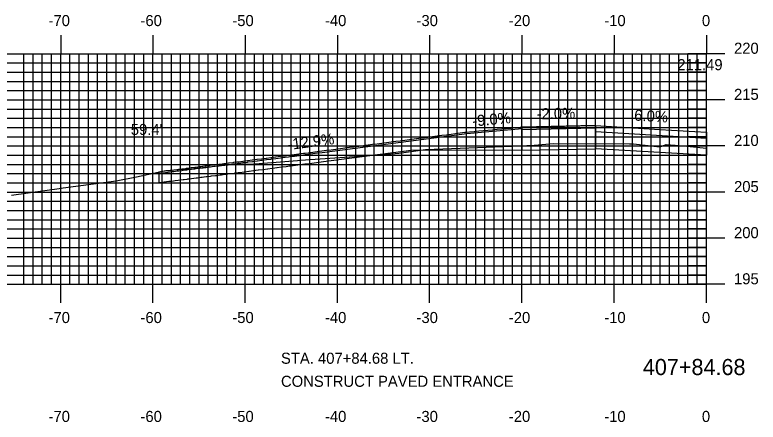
# Model space of a CAD drawing. Extents: x 852529 to 852872, y 364785 to 365005.
# Drawn here: x 852619.8 to 852700.3, y 364846.2 to 364890.4 of the extents above; entities that cross this region are included whole.
import ezdxf

# ---------------------------------------------------------------- set-up
doc = ezdxf.new("R2010")
doc.units = 0
for name, color, linetype in [('ANNOTATION', 7, 'Continuous'), ('D_Roadway_Centerline', 7, 'Continuous'), ('D_Roadway_Centerline_Text', 7, 'Continuous'), ('D_Roadway_Drive_Paved_LT', 7, 'Continuous'), ('D_Roadway_Drive_SubGrade', 7, 'Continuous'), ('D_Roadway_Edge_Shoulder', 7, 'Continuous'), ('D_Roadway_SlopeLines', 7, 'Continuous'), ('D_Text_Standard', 7, 'Continuous'), ('H_V ANNOTATION', 7, 'Continuous'), ('MAJOR', 7, 'Continuous'), ('MINOR', 7, 'Continuous'), ('S_Roadway_Centerline', 7, 'Continuous')]:
    doc.layers.add(name, color=color, linetype=linetype)

msp = doc.modelspace()

# ---------------------------------------------------------------- linework, layer by layer
at = {"layer": 'ANNOTATION'}
for p, q in [((852674.731, 364878.208), (852674.731, 364875.708)), ((852682.731, 364878.368), (852682.731, 364877.701)), ((852682.731, 364878.368), (852682.731, 364875.868)), ((852674.731, 364875.708), (852682.731, 364875.868))]:
    msp.add_line(p, q, dxfattribs=at)
for points in [[(852694.731, 364877.648), (852694.731, 364876.981), (852682.731, 364877.701)], [(852694.731, 364877.648), (852694.731, 364875.148), (852682.731, 364875.868)]]:
    msp.add_lwpolyline(points, dxfattribs=at)
at = {"layer": 'D_Roadway_Centerline'}
for points in [[(852635.377, 364873.373), (852635.536, 364873.392), (852635.757, 364873.42), (852636.076, 364873.46), (852636.283, 364873.485), (852636.316, 364873.489), (852636.37, 364873.496), (852636.533, 364873.515), (852636.807, 364873.55), (852636.992, 364873.572), (852637.33, 364873.615), (852637.503, 364873.635), (852637.851, 364873.68), (852637.983, 364873.696), (852638.274, 364873.733), (852638.303, 364873.736), (852638.371, 364873.745), (852638.522, 364873.763), (852638.889, 364873.81), (852639.271, 364873.858), (852639.406, 364873.875), (852639.797, 364873.925), (852639.922, 364873.94), (852640.105, 364873.963), (852640.16, 364873.97), (852640.375, 364873.997), (852640.437, 364874.005), (852640.845, 364874.057), (852640.95, 364874.07), (852641.366, 364874.123), (852641.463, 364874.135), (852641.886, 364874.189), (852641.974, 364874.2), (852642.021, 364874.206), (852642.03, 364874.207), (852642.414, 364874.256), (852642.485, 364874.265), (852642.922, 364874.321), (852642.994, 364874.33), (852643.438, 364874.387), (852643.503, 364874.395), (852643.843, 364874.439), (852643.887, 364874.444), (852643.997, 364874.458), (852644.01, 364874.46), (852644.467, 364874.519), (852644.517, 364874.525), (852644.979, 364874.584), (852645.023, 364874.59), (852645.49, 364874.65), (852645.528, 364874.655), (852645.718, 364874.679), (852645.733, 364874.681), (852646.014, 364874.717), (852646.033, 364874.72), (852646.509, 364874.781), (852646.537, 364874.785), (852647.017, 364874.847), (852647.041, 364874.85), (852647.524, 364874.912), (852647.544, 364874.915), (852647.569, 364874.918), (852647.57, 364874.918), (852648.031, 364874.978), (852648.046, 364874.98), (852648.535, 364875.043), (852648.548, 364875.045), (852649.04, 364875.109), (852649.05, 364875.11), (852649.395, 364875.155), (852649.401, 364875.155), (852649.549, 364875.174), (852649.551, 364875.175), (852650.046, 364875.239), (852650.052, 364875.24), (852650.549, 364875.304), (852650.552, 364875.305), (852651.051, 364875.369), (852651.053, 364875.37), (852651.227, 364875.392), (852651.227, 364875.392), (852651.552, 364875.435), (852651.553, 364875.435), (852652.053, 364875.5), (852652.053, 364875.5), (852652.288, 364875.53), (852652.553, 364875.565), (852652.553, 364875.565), (852653.051, 364875.629), (852653.053, 364875.63), (852653.053, 364875.63), (852653.053, 364875.63), (852653.553, 364875.695), (852653.553, 364875.695), (852654.053, 364875.76), (852654.053, 364875.76), (852654.553, 364875.825), (852654.553, 364875.825), (852655.053, 364875.89), (852655.053, 364875.89), (852655.553, 364875.955), (852655.553, 364875.955), (852656.053, 364876.02), (852656.053, 364876.02), (852656.553, 364876.085), (852656.553, 364876.085), (852657.053, 364876.15), (852657.053, 364876.15), (852657.553, 364876.215), (852657.553, 364876.215), (852658.053, 364876.28), (852658.053, 364876.28), (852658.553, 364876.345), (852658.553, 364876.345), (852659.053, 364876.41), (852659.053, 364876.41), (852659.553, 364876.475), (852659.553, 364876.475), (852660.053, 364876.54), (852660.053, 364876.54), (852660.553, 364876.605), (852660.553, 364876.605), (852661.053, 364876.67), (852661.053, 364876.67), (852661.553, 364876.735), (852661.553, 364876.735), (852662.053, 364876.8), (852662.053, 364876.8), (852662.553, 364876.865), (852662.553, 364876.865), (852663.053, 364876.93), (852663.053, 364876.93), (852663.553, 364876.995), (852663.553, 364876.995), (852664.053, 364877.06), (852664.053, 364877.06), (852664.553, 364877.125), (852664.553, 364877.125), (852665.053, 364877.19), (852665.053, 364877.19), (852665.553, 364877.255), (852665.553, 364877.255), (852666.053, 364877.32), (852666.053, 364877.32), (852666.553, 364877.385), (852666.553, 364877.385), (852667.053, 364877.45), (852667.053, 364877.45), (852667.553, 364877.515), (852667.553, 364877.515), (852668.053, 364877.58), (852668.053, 364877.58), (852668.553, 364877.645), (852668.553, 364877.645), (852668.735, 364877.668), (852668.735, 364877.668), (852669.053, 364877.697), (852669.053, 364877.697), (852669.553, 364877.742), (852669.553, 364877.742), (852670.053, 364877.787), (852670.053, 364877.787), (852670.553, 364877.832), (852670.553, 364877.832), (852671.053, 364877.877), (852671.053, 364877.877), (852671.553, 364877.922), (852671.553, 364877.922), (852672.053, 364877.967), (852672.053, 364877.967), (852672.553, 364878.012), (852672.553, 364878.012), (852673.053, 364878.057), (852673.053, 364878.057), (852673.553, 364878.102), (852673.553, 364878.102), (852674.053, 364878.147), (852674.053, 364878.147), (852674.553, 364878.192), (852674.553, 364878.192), (852674.731, 364878.208), (852674.731, 364878.208)], [(852674.731, 364878.208), (852679.341, 364878.3), (852682.731, 364878.368), (852689.67, 364877.952), (852694.731, 364877.648)]]:
    msp.add_lwpolyline(points, dxfattribs=at)
at = {"layer": 'D_Roadway_Drive_Paved_LT'}
msp.add_line((852635.377, 364873.373), (852635.377, 364873.205), dxfattribs=at)
msp.add_lwpolyline([(852635.377, 364873.205), (852635.557, 364873.226), (852636.096, 364873.295), (852636.337, 364873.323), (852636.39, 364873.33), (852636.554, 364873.35), (852636.827, 364873.384), (852637.012, 364873.406), (852637.35, 364873.449), (852637.523, 364873.47), (852637.871, 364873.514), (852638.004, 364873.53), (852638.295, 364873.567), (852638.323, 364873.571), (852638.391, 364873.579), (852638.542, 364873.597), (852639.291, 364873.693), (852639.427, 364873.709), (852639.817, 364873.759), (852639.943, 364873.774), (852640.125, 364873.798), (852640.181, 364873.804), (852640.396, 364873.832), (852640.457, 364873.839), (852640.865, 364873.892), (852640.971, 364873.904), (852641.387, 364873.958), (852641.483, 364873.969), (852641.907, 364874.024), (852641.995, 364874.034), (852642.041, 364874.04), (852642.051, 364874.041), (852642.434, 364874.091), (852642.505, 364874.099), (852642.943, 364874.156), (852643.015, 364874.164), (852643.459, 364874.222), (852643.523, 364874.229), (852643.863, 364874.273), (852643.908, 364874.279), (852644.017, 364874.293), (852644.031, 364874.294), (852644.487, 364874.353), (852644.538, 364874.359), (852645, 364874.419), (852645.044, 364874.424), (852645.511, 364874.485), (852645.549, 364874.489), (852645.739, 364874.514), (852645.754, 364874.516), (852646.034, 364874.552), (852646.054, 364874.554), (852646.53, 364874.616), (852646.558, 364874.619), (852647.038, 364874.681), (852647.061, 364874.684), (852647.545, 364874.747), (852647.564, 364874.749), (852647.59, 364874.753), (852647.591, 364874.753), (852648.052, 364874.813), (852648.067, 364874.814), (852648.556, 364874.878), (852648.569, 364874.879), (852649.06, 364874.943), (852649.07, 364874.944), (852649.416, 364874.989), (852649.421, 364874.99), (852649.569, 364875.009), (852649.572, 364875.009), (852650.067, 364875.074), (852650.072, 364875.074), (852650.57, 364875.139), (852650.573, 364875.139), (852651.071, 364875.204), (852651.073, 364875.204), (852651.247, 364875.227), (852651.248, 364875.227), (852651.573, 364875.269), (852651.574, 364875.269), (852652.074, 364875.334), (852652.074, 364875.334), (852652.575, 364875.4), (852652.576, 364875.4), (852653.075, 364875.465), (852653.076, 364875.465), (852668.753, 364877.503), (852674.746, 364878.042)], dxfattribs=at)
at = {"layer": 'D_Roadway_Drive_SubGrade'}
for p, q in [((852673.731, 364875.688), (852662.731, 364875.711)), ((852674.731, 364875.708), (852673.731, 364875.688)), ((852635.377, 364873.205), (852635.377, 364872.198))]:
    msp.add_line(p, q, dxfattribs=at)
msp.add_lwpolyline([(852635.377, 364872.198), (852635.678, 364872.234), (852636.218, 364872.302), (852636.459, 364872.331), (852636.512, 364872.338), (852636.676, 364872.357), (852636.949, 364872.392), (852637.135, 364872.414), (852637.472, 364872.457), (852637.646, 364872.477), (852637.994, 364872.522), (852638.126, 364872.538), (852638.417, 364872.575), (852638.446, 364872.578), (852638.514, 364872.587), (852638.665, 364872.605), (852639.414, 364872.701), (852639.55, 364872.717), (852639.94, 364872.767), (852640.066, 364872.782), (852640.249, 364872.805), (852640.304, 364872.812), (852640.519, 364872.84), (852640.581, 364872.847), (852640.988, 364872.899), (852641.094, 364872.912), (852641.51, 364872.965), (852641.607, 364872.977), (852642.03, 364873.031), (852642.118, 364873.042), (852642.165, 364873.048), (852642.174, 364873.049), (852642.558, 364873.098), (852642.629, 364873.107), (852643.067, 364873.163), (852643.138, 364873.172), (852643.583, 364873.229), (852643.647, 364873.237), (852643.987, 364873.281), (852644.032, 364873.286), (852644.141, 364873.3), (852644.155, 364873.302), (852644.611, 364873.361), (852644.662, 364873.367), (852645.124, 364873.427), (852645.168, 364873.432), (852645.635, 364873.492), (852645.673, 364873.497), (852645.863, 364873.522), (852645.878, 364873.523), (852646.158, 364873.56), (852646.178, 364873.562), (852646.654, 364873.624), (852646.682, 364873.627), (852647.162, 364873.689), (852647.186, 364873.692), (852647.669, 364873.755), (852647.689, 364873.757), (852647.714, 364873.76), (852647.715, 364873.761), (852648.176, 364873.82), (852648.191, 364873.822), (852648.68, 364873.886), (852648.693, 364873.887), (852649.185, 364873.951), (852649.195, 364873.952), (852649.54, 364873.997), (852649.546, 364873.998), (852649.694, 364874.017), (852649.696, 364874.017), (852650.191, 364874.081), (852650.197, 364874.082), (852650.694, 364874.147), (852650.697, 364874.147), (852651.196, 364874.212), (852651.198, 364874.212), (852651.371, 364874.235), (852651.372, 364874.235), (852651.697, 364874.277), (852651.698, 364874.277), (852652.198, 364874.342), (852652.198, 364874.342), (852652.71, 364874.409), (852652.71, 364874.409), (852653.21, 364874.474), (852653.21, 364874.474), (852662.731, 364875.711)], dxfattribs=at)
at = {"layer": 'D_Roadway_Edge_Shoulder'}
msp.add_lwpolyline([(852682.731, 364878.368), (852674.731, 364878.208), (852674.731, 364877.958), (852682.731, 364878.118)], close=True, dxfattribs=at)
at = {"layer": 'D_Roadway_SlopeLines'}
msp.add_lwpolyline([(852674.731, 364878.208), (852674.731, 364878.208)], dxfattribs=at)
at = {"layer": 'MAJOR'}
for p, q in [((852624.731, 364888.165), (852624.731, 364886.161)), ((852634.731, 364888.165), (852634.731, 364886.161)), ((852644.731, 364888.165), (852644.731, 364886.161)), ((852654.731, 364888.165), (852654.731, 364886.161)), ((852664.731, 364888.165), (852664.731, 364886.161)), ((852674.731, 364888.165), (852674.731, 364886.161)), ((852684.731, 364888.165), (852684.731, 364886.161)), ((852694.731, 364888.165), (852694.731, 364886.161)), ((852554.731, 364886.161), (852694.731, 364886.161)), ((852554.731, 364886.161), (852694.731, 364886.161)), ((852624.731, 364861.161), (852624.731, 364886.161)), ((852634.731, 364861.161), (852634.731, 364886.161)), ((852644.731, 364861.161), (852644.731, 364886.161)), ((852654.731, 364861.161), (852654.731, 364886.161)), ((852664.731, 364861.161), (852664.731, 364886.161)), ((852674.731, 364861.161), (852674.731, 364886.161)), ((852684.731, 364861.161), (852684.731, 364886.161)), ((852696.735, 364886.161), (852692.727, 364886.161)), ((852694.731, 364861.161), (852694.731, 364886.161)), ((852694.731, 364861.161), (852694.731, 364886.161)), ((852554.731, 364881.161), (852694.731, 364881.161)), ((852696.735, 364881.161), (852692.727, 364881.161)), ((852554.731, 364876.161), (852694.731, 364876.161)), ((852696.735, 364876.161), (852692.727, 364876.161)), ((852554.731, 364871.161), (852694.731, 364871.161)), ((852696.735, 364871.161), (852692.727, 364871.161)), ((852554.731, 364866.161), (852694.731, 364866.161)), ((852696.735, 364866.161), (852692.727, 364866.161)), ((852554.731, 364861.161), (852694.731, 364861.161)), ((852554.731, 364861.161), (852694.731, 364861.161)), ((852624.731, 364859.157), (852624.731, 364861.161)), ((852634.731, 364859.157), (852634.731, 364861.161)), ((852644.731, 364859.157), (852644.731, 364861.161)), ((852654.731, 364859.157), (852654.731, 364861.161)), ((852664.731, 364859.157), (852664.731, 364861.161)), ((852674.731, 364859.157), (852674.731, 364861.161)), ((852684.731, 364859.157), (852684.731, 364861.161)), ((852696.735, 364861.161), (852692.727, 364861.161)), ((852694.731, 364859.157), (852694.731, 364861.161))]:
    msp.add_line(p, q, dxfattribs=at)
at = {"layer": 'MINOR'}
for p, q in [((852620.731, 364861.161), (852620.731, 364886.161)), ((852621.731, 364861.161), (852621.731, 364886.161)), ((852622.731, 364861.161), (852622.731, 364886.161)), ((852623.731, 364861.161), (852623.731, 364886.161)), ((852625.731, 364861.161), (852625.731, 364886.161)), ((852626.731, 364861.161), (852626.731, 364886.161)), ((852627.731, 364861.161), (852627.731, 364886.161)), ((852628.731, 364861.161), (852628.731, 364886.161)), ((852629.731, 364861.161), (852629.731, 364886.161)), ((852630.731, 364861.161), (852630.731, 364886.161)), ((852631.731, 364861.161), (852631.731, 364886.161)), ((852632.731, 364861.161), (852632.731, 364886.161)), ((852633.731, 364861.161), (852633.731, 364886.161)), ((852635.731, 364861.161), (852635.731, 364886.161)), ((852636.731, 364861.161), (852636.731, 364886.161)), ((852637.731, 364861.161), (852637.731, 364886.161)), ((852638.731, 364861.161), (852638.731, 364886.161)), ((852639.731, 364861.161), (852639.731, 364886.161)), ((852640.731, 364861.161), (852640.731, 364886.161)), ((852641.731, 364861.161), (852641.731, 364886.161)), ((852642.731, 364861.161), (852642.731, 364886.161)), ((852643.731, 364861.161), (852643.731, 364886.161)), ((852645.731, 364861.161), (852645.731, 364886.161)), ((852646.731, 364861.161), (852646.731, 364886.161)), ((852647.731, 364861.161), (852647.731, 364886.161)), ((852648.731, 364861.161), (852648.731, 364886.161)), ((852649.731, 364861.161), (852649.731, 364886.161)), ((852650.731, 364861.161), (852650.731, 364886.161)), ((852651.731, 364861.161), (852651.731, 364886.161)), ((852652.731, 364861.161), (852652.731, 364886.161)), ((852653.731, 364861.161), (852653.731, 364886.161)), ((852655.731, 364861.161), (852655.731, 364886.161)), ((852656.731, 364861.161), (852656.731, 364886.161)), ((852657.731, 364861.161), (852657.731, 364886.161)), ((852658.731, 364861.161), (852658.731, 364886.161)), ((852659.731, 364861.161), (852659.731, 364886.161)), ((852660.731, 364861.161), (852660.731, 364886.161)), ((852661.731, 364861.161), (852661.731, 364886.161)), ((852662.731, 364861.161), (852662.731, 364886.161)), ((852663.731, 364861.161), (852663.731, 364886.161)), ((852665.731, 364861.161), (852665.731, 364886.161)), ((852666.731, 364861.161), (852666.731, 364886.161)), ((852667.731, 364861.161), (852667.731, 364886.161)), ((852668.731, 364861.161), (852668.731, 364886.161)), ((852669.731, 364861.161), (852669.731, 364886.161)), ((852670.731, 364861.161), (852670.731, 364886.161)), ((852671.731, 364861.161), (852671.731, 364886.161)), ((852672.731, 364861.161), (852672.731, 364886.161)), ((852673.731, 364861.161), (852673.731, 364886.161)), ((852675.731, 364861.161), (852675.731, 364886.161)), ((852676.731, 364861.161), (852676.731, 364886.161)), ((852677.731, 364861.161), (852677.731, 364886.161)), ((852678.731, 364861.161), (852678.731, 364886.161)), ((852679.731, 364861.161), (852679.731, 364886.161)), ((852680.731, 364861.161), (852680.731, 364886.161)), ((852681.731, 364861.161), (852681.731, 364886.161)), ((852682.731, 364861.161), (852682.731, 364886.161)), ((852683.731, 364861.161), (852683.731, 364886.161)), ((852685.731, 364861.161), (852685.731, 364886.161)), ((852686.731, 364861.161), (852686.731, 364886.161)), ((852687.731, 364861.161), (852687.731, 364886.161)), ((852688.731, 364861.161), (852688.731, 364886.161)), ((852689.731, 364861.161), (852689.731, 364886.161)), ((852690.731, 364861.161), (852690.731, 364886.161)), ((852691.731, 364861.161), (852691.731, 364886.161)), ((852692.731, 364861.161), (852692.731, 364886.161)), ((852693.731, 364861.161), (852693.731, 364886.161)), ((852554.731, 364885.161), (852694.731, 364885.161)), ((852694.731, 364885.161), (852692.727, 364885.161)), ((852554.731, 364884.161), (852694.731, 364884.161)), ((852694.731, 364884.161), (852692.727, 364884.161)), ((852554.731, 364883.161), (852694.731, 364883.161)), ((852694.731, 364883.161), (852692.727, 364883.161)), ((852554.731, 364882.161), (852694.731, 364882.161)), ((852694.731, 364882.161), (852692.727, 364882.161)), ((852554.731, 364880.161), (852694.731, 364880.161)), ((852694.731, 364880.161), (852692.727, 364880.161)), ((852554.731, 364879.161), (852694.731, 364879.161)), ((852694.731, 364879.161), (852692.727, 364879.161)), ((852554.731, 364878.161), (852694.731, 364878.161)), ((852694.731, 364878.161), (852692.727, 364878.161)), ((852554.731, 364877.161), (852694.731, 364877.161)), ((852694.731, 364877.161), (852692.727, 364877.161)), ((852554.731, 364875.161), (852694.731, 364875.161)), ((852694.731, 364875.161), (852692.727, 364875.161)), ((852554.731, 364874.161), (852694.731, 364874.161)), ((852694.731, 364874.161), (852692.727, 364874.161)), ((852554.731, 364873.161), (852694.731, 364873.161)), ((852694.731, 364873.161), (852692.727, 364873.161)), ((852554.731, 364872.161), (852694.731, 364872.161)), ((852694.731, 364872.161), (852692.727, 364872.161)), ((852554.731, 364870.161), (852694.731, 364870.161)), ((852694.731, 364870.161), (852692.727, 364870.161)), ((852554.731, 364869.161), (852694.731, 364869.161)), ((852694.731, 364869.161), (852692.727, 364869.161)), ((852554.731, 364868.161), (852694.731, 364868.161)), ((852694.731, 364868.161), (852692.727, 364868.161)), ((852554.731, 364867.161), (852694.731, 364867.161)), ((852694.731, 364867.161), (852692.727, 364867.161)), ((852554.731, 364865.161), (852694.731, 364865.161)), ((852694.731, 364865.161), (852692.727, 364865.161)), ((852554.731, 364864.161), (852694.731, 364864.161)), ((852694.731, 364864.161), (852692.727, 364864.161)), ((852554.731, 364863.161), (852694.731, 364863.161)), ((852694.731, 364863.161), (852692.727, 364863.161)), ((852554.731, 364862.161), (852694.731, 364862.161)), ((852694.731, 364862.161), (852692.727, 364862.161))]:
    msp.add_line(p, q, dxfattribs=at)
at = {"layer": 'S_Roadway_Centerline'}
msp.add_lwpolyline([(852619.399, 364870.835), (852624.828, 364871.601), (852625.007, 364871.619), (852630.729, 364872.396), (852632.949, 364872.814), (852636.129, 364873.488), (852637.932, 364873.63), (852638.273, 364873.611), (852640.379, 364873.861), (852643.255, 364874.162), (852643.626, 364874.174), (852645.785, 364874.239), (852650.41, 364874.599), (852650.713, 364874.62), (852659.77, 364875.253), (852661.387, 364875.396), (852664.266, 364875.774), (852673.676, 364876.133), (852676.067, 364876.243), (852678.144, 364876.426), (852686.409, 364876.387), (852686.762, 364876.383), (852686.836, 364876.379), (852689.696, 364876.051), (852690.289, 364876.301), (852690.369, 364876.32), (852691.361, 364876.261), (852692.263, 364876.193), (852694.731, 364875.911)], dxfattribs=at)

# ---------------------------------------------------------------- texts
at = {"layer": 'ANNOTATION'}
for s, rotation, p in [('-9.0%', 5.14337, (852669.404, 364878.265)), ('-2.0%', 1.14576, (852676.337, 364879.041)), ('6.0%', 356.56637, (852686.885, 364878.922)), ('-12.9%', 7.33759, (852649.409, 364875.718))]:
    msp.add_text(s, height=1.2, rotation=rotation, dxfattribs=at).set_placement(p)
at = {"layer": 'D_Roadway_Centerline_Text'}
msp.add_text('211.49', height=1.2, dxfattribs=at).set_placement((852691.583, 364884.377))
at = {"layer": 'D_Text_Standard'}
for s, p in [("59.4'", (852632.332, 364877.353)), ('STA. 407+84.68 LT.', (852648.615, 364852.545)), ('CONSTRUCT PAVED ENTRANCE', (852648.615, 364850.045))]:
    msp.add_text(s, height=1.2, dxfattribs=at).set_placement(p)
at = {"layer": 'H_V ANNOTATION'}
for s, height, p in [('-70', 1.2, (852623.414, 364889.161)), ('-60', 1.2, (852633.382, 364889.161)), ('-50', 1.2, (852643.339, 364889.161)), ('-40', 1.2, (852653.382, 364889.161)), ('-30', 1.2, (852663.307, 364889.161)), ('-20', 1.2, (852673.318, 364889.161)), ('-10', 1.2, (852683.66, 364889.161)), ('0', 1.2, (852694.249, 364889.161)), ('220', 1.2, (852697.731, 364886.161)), ('215', 1.2, (852697.731, 364881.161)), ('210', 1.2, (852697.731, 364876.161)), ('205', 1.2, (852697.731, 364871.161)), ('200', 1.2, (852697.731, 364866.161)), ('195', 1.2, (852697.731, 364861.161)), ('-70', 1.2, (852623.414, 364856.961)), ('-60', 1.2, (852633.382, 364856.961)), ('-50', 1.2, (852643.339, 364856.961)), ('-40', 1.2, (852653.382, 364856.961)), ('-30', 1.2, (852663.307, 364856.961)), ('-20', 1.2, (852673.318, 364856.961)), ('-10', 1.2, (852683.66, 364856.961)), ('0', 1.2, (852694.249, 364856.961)), ('407+84.68', 1.75, (852687.847, 364851.317)), ('-70', 1.2, (852623.414, 364846.233)), ('-60', 1.2, (852633.382, 364846.233)), ('-50', 1.2, (852643.339, 364846.233)), ('-40', 1.2, (852653.382, 364846.233)), ('-30', 1.2, (852663.307, 364846.233)), ('-20', 1.2, (852673.318, 364846.233)), ('-10', 1.2, (852683.66, 364846.233)), ('0', 1.2, (852694.249, 364846.233))]:
    msp.add_text(s, height=height, dxfattribs=at).set_placement(p)

doc.saveas('drawing.dxf')
